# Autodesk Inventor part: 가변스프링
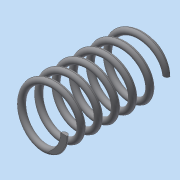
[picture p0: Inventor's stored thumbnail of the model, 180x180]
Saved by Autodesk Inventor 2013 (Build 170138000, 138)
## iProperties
Created: 2018-07
Part Number: 가변스프링
Material: 스테인리스강
Document SubType Name: Modeling
Designer: dgall
Density: 8.08 g/cm^3
Author: dgall
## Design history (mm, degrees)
sketch "스케치1"
  geometry: L1 (0, 0)-(0, 32.5); L2 (0, 0)-(8, 0); L3 (0, 32.5)-(8, 32.5); C1 r 1 at (8, 0)
  constraints: 6 end point, 2 parallel, 1 centre point, 1 coincident, 1 perpendicular, 1 vertical
  dimensions: "d0" = 32.5 distance of L1.start L1.end (derived); "d1" = 16 diameter of L2.end L1; "d2" = 2 diameter of C1
feature "코일1" pitch "d3" = 10; turns "d5" = 6; dims "d4" = 32.5 (= d0), "d6" = 0, angle "d7" = 90 deg, angle "d8" = 90 deg, "d9" = 0, "d10" = 0
feature "분할1"
node "작업 평면1"
feature "분할2"
node "솔리드1"
